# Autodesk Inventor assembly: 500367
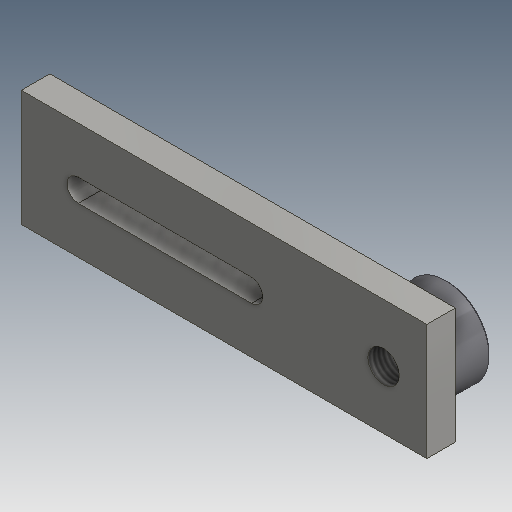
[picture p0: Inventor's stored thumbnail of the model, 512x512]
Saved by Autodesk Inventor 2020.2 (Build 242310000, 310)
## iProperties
Created: 2000-02
Part Number: 500367
Document SubType Name: Assembly
Description: WMT-RF,FH,DX,070,020,05,016,IDLER ADJ
Designer: glanglot
Mass: 910.861 g
Surface Area: 291.777 cm^2
Volume: 116.33 cm^3
Density: 7.83 g/cm^3
Control State: 0
Checked Out: False
Master: False
Shininess: 0.0
Length Units: 11272
Angle Units: 11279
Time Units: 11290
Mass Units: 11286
Length Display Precision: 3
Angle Display Precision: 2
Compacted: True
Dimensions: 2x1,1x7 in
Mass: 2,008 lb
Density: 0.0
Volumn: 0.0
Area: 0.0
PropertySet Name: Model Information
Author: glanglot
Revision Number: -
Title: WMT-RF,FH,DX,070,020,05,016,IDLER ADJ
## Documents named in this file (3)
- D:\07 - DEMODATEN\OTX 2019 - Dataset - UPDATE - Dez2019\Designs\07-Packing machine\500367.iam
- D:\07 - DEMODATEN\OTX 2019 - Dataset - UPDATE - Dez2019\Designs\07-Packing machine\Parts\ADSK-011350.ipt
- D:\07 - DEMODATEN\OTX 2019 - Dataset - UPDATE - Dez2019\Designs\07-Packing machine\Parts\ADSK-011349.ipt
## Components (2 placed, 2 different names)
1. ADSK-011349:1 — Einfügen:1
2. ADSK-011350:1 — Einfügen:1
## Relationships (1: Insert 1)
- Einfügen:1 [Insert]: ADSK-011349:1 ↔ ADSK-011350:1
